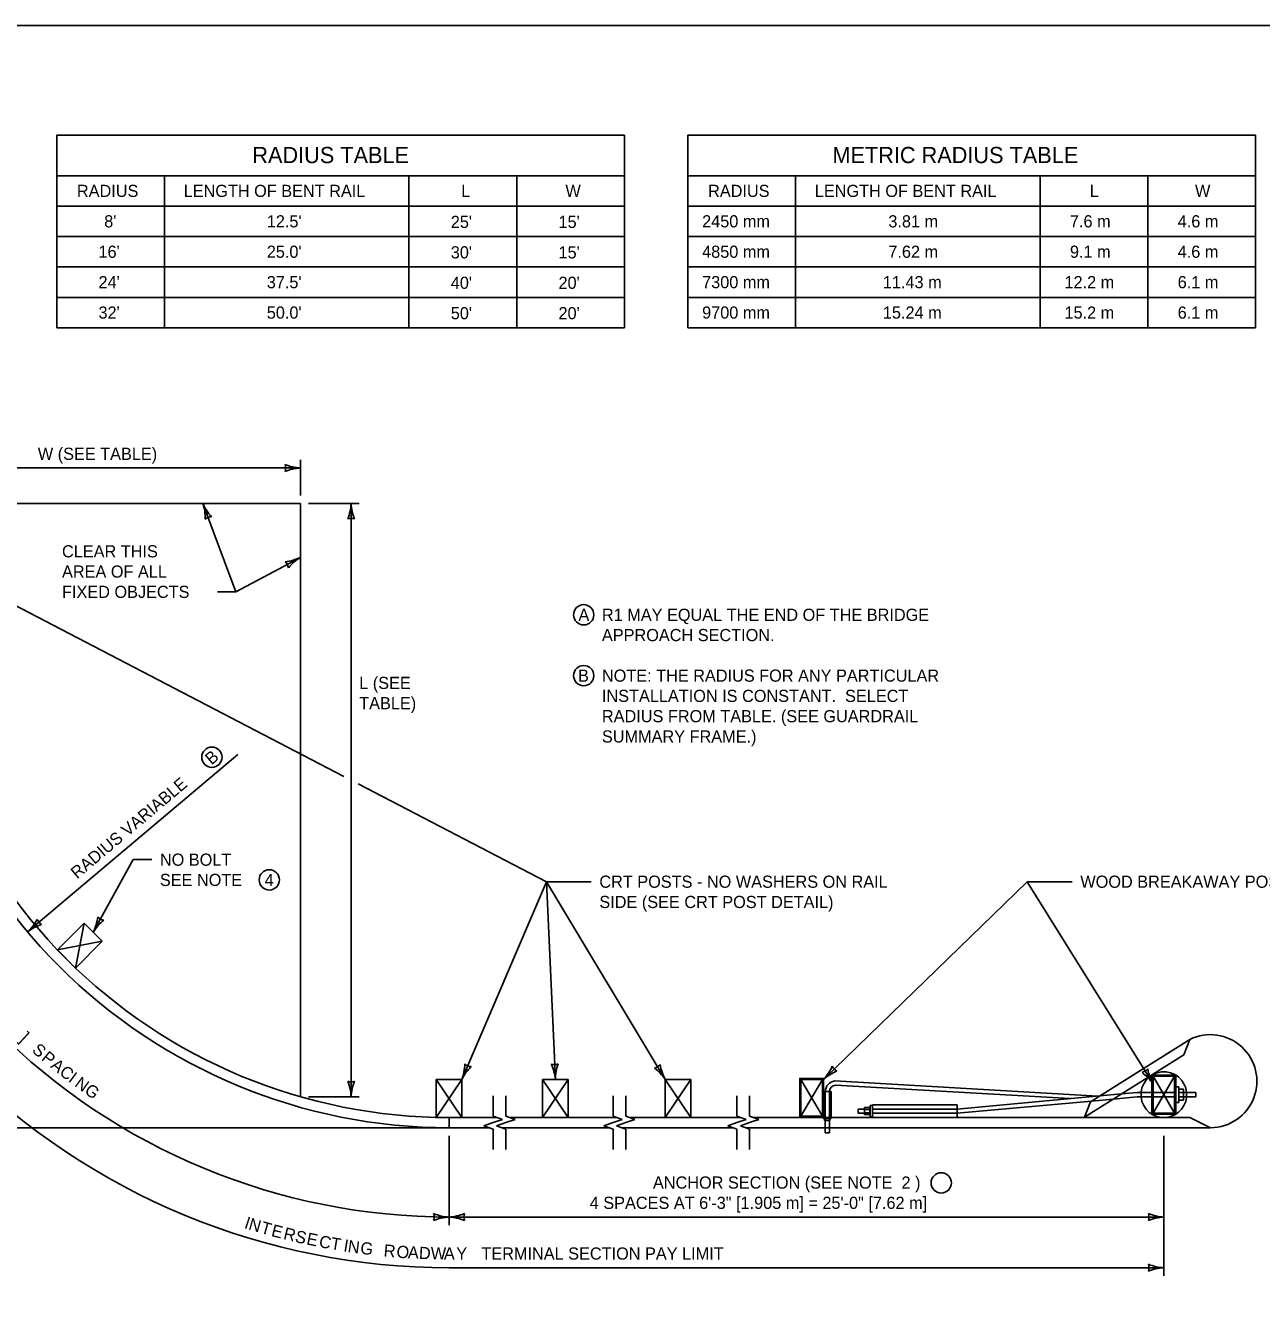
# Model space of a CAD drawing. Extents: x 49991.4 to 50021, y 49987.6 to 50011.4.
# Drawn here: x 50001.79 to 50007.89, y 49992.72 to 49999 of the extents above; entities that cross this region are included whole.
import ezdxf

# ---------------------------------------------------------------- set-up
doc = ezdxf.new("R2010")
doc.units = 0
for name, color, linetype in [('Level 1', 7, 'Continuous'), ('Level 2', 7, 'Continuous'), ('Level 3', 7, 'Continuous'), ('Level 4', 7, 'Continuous'), ('Level 6', 7, 'Continuous')]:
    doc.layers.add(name, color=color, linetype=linetype)

msp = doc.modelspace()

# ---------------------------------------------------------------- linework, layer by layer
at = {"layer": 'Level 1'}
for p, q in [((50003.1466, 49996.6418), (50001.2105, 49996.6418)), ((50003.1466, 49993.716), (50003.1466, 49996.6418)), ((50002.0803, 49994.5724), (50001.9477, 49994.4398)), ((50002.0802, 49994.5723), (50002.037, 49994.3504)), ((50002.1695, 49994.483), (50002.0803, 49994.5724)), ((50002.1695, 49994.483), (50001.9477, 49994.4398)), ((50002.1695, 49994.483), (50002.037, 49994.3504)), ((50001.9477, 49994.4398), (50002.037, 49994.3504)), ((50007.0428, 49993.6914), (50007.5328, 49993.9988)), ((50007.5041, 49993.9233), (50007.5328, 49993.9988)), ((50007.0141, 49993.6159), (50007.5041, 49993.9233)), ((50003.9428, 49993.8011), (50003.8166, 49993.8011)), ((50003.9428, 49993.6137), (50003.8166, 49993.8011)), ((50003.8166, 49993.6142), (50003.9428, 49993.8011)), ((50003.8166, 49993.6142), (50003.8166, 49993.8011)), ((50003.9428, 49993.6134), (50003.9428, 49993.8011)), ((50004.4671, 49993.8011), (50004.3408, 49993.8011)), ((50004.4671, 49993.6137), (50004.3408, 49993.8011)), ((50004.3408, 49993.6137), (50004.4671, 49993.8011)), ((50004.3408, 49993.6137), (50004.3408, 49993.8011)), ((50004.4671, 49993.6137), (50004.4671, 49993.8011)), ((50005.0721, 49993.8011), (50004.9458, 49993.8011)), ((50005.0721, 49993.6137), (50004.9458, 49993.8011)), ((50004.9458, 49993.6137), (50005.0721, 49993.8011)), ((50004.9458, 49993.6137), (50004.9458, 49993.8011)), ((50005.0721, 49993.6137), (50005.0721, 49993.8011)), ((50005.7214, 49993.8008), (50005.6153, 49993.6195)), ((50005.6153, 49993.8008), (50005.7214, 49993.6195)), ((50005.7829, 49993.7939), (50007.0798, 49993.7194)), ((50005.7851, 49993.7731), (50006.9421, 49993.7067)), ((50007.3517, 49993.817), (50007.4578, 49993.6357)), ((50007.4578, 49993.817), (50007.3517, 49993.6357)), ((50005.7271, 49993.7411), (50005.7638, 49993.7411)), ((50005.7271, 49993.6137), (50005.7271, 49993.7411)), ((50005.7638, 49993.6137), (50005.7638, 49993.7411)), ((50006.3848, 49993.6553), (50007.0887, 49993.7202)), ((50007.1557, 49993.7047), (50007.2729, 49993.7154)), ((50007.1965, 49993.7303), (50007.273, 49993.7372)), ((50007.3517, 49993.7154), (50007.2729, 49993.7154)), ((50007.3517, 49993.7372), (50007.273, 49993.7372)), ((50007.4635, 49993.7653), (50007.4782, 49993.7653)), ((50007.4782, 49993.7653), (50007.4782, 49993.6873)), ((50007.4782, 49993.7528), (50007.5023, 49993.7528)), ((50007.4782, 49993.7372), (50007.5628, 49993.7372)), ((50007.4782, 49993.7154), (50007.5628, 49993.7154)), ((50007.5023, 49993.7528), (50007.5023, 49993.6997)), ((50007.5628, 49993.7372), (50007.5628, 49993.7154)), ((50005.9281, 49993.6553), (50005.9291, 49993.6553)), ((50005.9291, 49993.6528), (50005.9546, 49993.6528)), ((50005.9678, 49993.6761), (50006.3848, 49993.6761)), ((50005.9678, 49993.6137), (50005.9678, 49993.6761)), ((50006.3848, 49993.6346), (50007.0484, 49993.6949)), ((50006.3848, 49993.6137), (50006.3848, 49993.6761)), ((50007.0141, 49993.6159), (50007.0428, 49993.6914)), ((50007.4635, 49993.6873), (50007.4782, 49993.6873)), ((50007.4782, 49993.6997), (50007.5023, 49993.6997)), ((50003.8797, 49993.6134), (50004.1177, 49993.6134)), ((50003.8797, 49993.5631), (50003.8797, 49993.6134)), ((50004.1794, 49993.6137), (50004.7084, 49993.6137)), ((50004.7709, 49993.6137), (50005.3197, 49993.6137)), ((50005.3822, 49993.6137), (50007.5328, 49993.6137)), ((50005.7271, 49993.6083), (50005.7271, 49993.6137)), ((50005.7271, 49993.6083), (50005.7638, 49993.6083)), ((50005.7638, 49993.6083), (50005.7638, 49993.6137)), ((50005.9281, 49993.6345), (50005.9291, 49993.6345)), ((50005.9291, 49993.637), (50005.9546, 49993.637)), ((50007.5328, 49993.6137), (50007.6356, 49993.5631)), ((50003.8797, 49993.5631), (50004.0768, 49993.5631)), ((50004.1393, 49993.5631), (50004.6683, 49993.5631)), ((50004.7308, 49993.5631), (50005.2796, 49993.5631)), ((50005.3421, 49993.5631), (50007.6356, 49993.5631)), ((50005.735, 49993.5631), (50005.735, 49993.5378)), ((50005.735, 49993.5378), (50005.7559, 49993.5378)), ((50005.7559, 49993.5631), (50005.7559, 49993.5378))]:
    msp.add_line(p, q, dxfattribs=at)
for points in [[(49999.3835, 49998.9992), (50016.7501, 49998.9992), (50016.7501, 49987.7988), (49999.3835, 49987.7988)], [(50005.6153, 49993.8008), (50005.7214, 49993.8008), (50005.7214, 49993.6195), (50005.6153, 49993.6195)], [(50007.3517, 49993.817), (50007.4578, 49993.817), (50007.4578, 49993.6357), (50007.3517, 49993.6357)], [(50005.9281, 49993.6553), (50005.9281, 49993.6345), (50005.8978, 49993.6345), (50005.8978, 49993.6553)], [(50005.9291, 49993.6625), (50005.9291, 49993.6281), (50005.9546, 49993.6281), (50005.9546, 49993.6625)], [(50005.9558, 49993.6727), (50005.9558, 49993.6164), (50005.9678, 49993.6164), (50005.9678, 49993.6727)], [(50005.7318, 49993.6083), (50005.7318, 49993.5994), (50005.7581, 49993.5994), (50005.7581, 49993.6083)]]:
    msp.add_lwpolyline(points, close=True, dxfattribs=at)
for points in [[(50005.6095, 49993.721), (50005.6095, 49993.8066), (50005.7271, 49993.8066), (50005.7271, 49993.6137), (50005.6095, 49993.6137), (50005.6095, 49993.721)], [(50007.3459, 49993.7372), (50007.3459, 49993.8228), (50007.4635, 49993.8228), (50007.4635, 49993.6299), (50007.3459, 49993.6299), (50007.3459, 49993.7154)], [(50007.3459, 49993.7154), (50007.3459, 49993.7372)]]:
    msp.add_lwpolyline(points, dxfattribs=at)
for centre, radius, start, end in [((50003.8796, 49996.2825), 2.7194, 180, 270.00211), ((50003.8796, 49996.2825), 2.6691, 180, 270.00108), ((50007.6341, 49993.7927), 0.2296, 270.3943, 116.15709), ((50007.4048, 49993.7263), 0.113, 185.54991, 185.5335), ((50007.284, 49993.8885), 0.0548, 284.01902, 319.74138), ((50007.1602, 49993.647), 0.233, 34.70751, 53.95736), ((50007.5452, 49993.8892), 0.2223, 189.33621, 209.51972), ((50005.7884, 49993.7408), 0.0534, 95.95713, 179.63592), ((50005.7884, 49993.7408), 0.0325, 95.95713, 179.40205)]:
    msp.add_arc(centre, radius, start, end, dxfattribs=at)
at = {"layer": 'Level 2'}
for p, q in [((50001.9444, 49998.4584), (50001.9444, 49997.5084)), ((50001.9444, 49998.4584), (50004.7446, 49998.4584)), ((50004.7446, 49998.4584), (50004.7446, 49997.5084)), ((50005.0573, 49998.4584), (50005.0573, 49997.5084)), ((50005.0573, 49998.4584), (50007.8575, 49998.4584)), ((50007.8575, 49998.4584), (50007.8575, 49997.5084)), ((50001.9444, 49998.2584), (50004.7446, 49998.2584)), ((50002.4758, 49998.2584), (50002.4758, 49998.1084)), ((50003.6819, 49998.2584), (50003.6819, 49997.5084)), ((50004.2133, 49998.2584), (50004.2133, 49997.5084)), ((50005.0573, 49998.2584), (50007.8575, 49998.2584)), ((50005.5887, 49998.2584), (50005.5887, 49998.1084)), ((50006.7948, 49998.2584), (50006.7948, 49997.5084)), ((50007.3262, 49998.2584), (50007.3262, 49997.5084)), ((50001.9444, 49998.1084), (50004.7446, 49998.1084)), ((50002.4758, 49998.1084), (50002.4758, 49997.9584)), ((50005.0573, 49998.1084), (50007.8575, 49998.1084)), ((50005.5887, 49998.1084), (50005.5887, 49997.9584)), ((50001.9444, 49997.9584), (50004.7446, 49997.9584)), ((50002.4758, 49997.9584), (50002.4758, 49997.8084)), ((50005.0573, 49997.9584), (50007.8575, 49997.9584)), ((50005.5887, 49997.9584), (50005.5887, 49997.8084)), ((50001.9444, 49997.8084), (50004.7446, 49997.8084)), ((50002.4758, 49997.8084), (50002.4758, 49997.6584)), ((50005.0573, 49997.8084), (50007.8575, 49997.8084)), ((50005.5887, 49997.8084), (50005.5887, 49997.6584)), ((50001.9444, 49997.6584), (50004.7446, 49997.6584)), ((50002.4758, 49997.6584), (50002.4758, 49997.5084)), ((50005.0573, 49997.6584), (50007.8575, 49997.6584)), ((50005.5887, 49997.6584), (50005.5887, 49997.5084)), ((50001.9444, 49997.5084), (50002.4758, 49997.5084)), ((50002.4758, 49997.5084), (50003.6819, 49997.5084)), ((50003.6819, 49997.5084), (50004.2133, 49997.5084)), ((50004.2133, 49997.5084), (50004.7446, 49997.5084)), ((50005.0573, 49997.5084), (50005.5887, 49997.5084)), ((50005.5887, 49997.5084), (50006.7948, 49997.5084)), ((50006.7948, 49997.5084), (50007.3262, 49997.5084)), ((50007.3262, 49997.5084), (50007.8575, 49997.5084))]:
    msp.add_line(p, q, dxfattribs=at)
for centre in [(50004.5436, 49996.0929), (50004.5436, 49995.7927), (50002.71, 49995.3904), (50002.9932, 49994.7853), (50006.3069, 49993.2912)]:
    msp.add_circle(centre, 0.05, dxfattribs=at)
at = {"layer": 'Level 3'}
for p, q in [((50003.1466, 49996.6818), (50003.1466, 49996.8568)), ((50001.2105, 49996.8168), (50003.1466, 49996.8168)), ((50002.8288, 49996.206), (50002.6657, 49996.6418)), ((50003.1866, 49996.6418), (50003.4366, 49996.6418)), ((50003.3966, 49993.716), (50003.3966, 49996.6418)), ((50002.8288, 49996.206), (50003.1466, 49996.3757)), ((50001.5855, 49996.2195), (50003.3612, 49995.2959)), ((50002.7377, 49996.206), (50002.8288, 49996.206)), ((50002.8383, 49995.404), (50001.8012, 49994.529)), ((50003.4321, 49995.259), (50004.3595, 49994.7766)), ((50002.3223, 49994.8853), (50002.1249, 49994.5277)), ((50002.3223, 49994.8853), (50002.4135, 49994.8853)), ((50004.3595, 49994.7766), (50003.9428, 49993.8011)), ((50004.3595, 49994.7766), (50004.4039, 49993.8011)), ((50004.3595, 49994.7766), (50004.9458, 49993.8011)), ((50004.3595, 49994.7766), (50004.5809, 49994.7766)), ((50006.7316, 49994.7766), (50005.7263, 49993.8011)), ((50006.7316, 49994.7766), (50007.3517, 49993.7796)), ((50006.7316, 49994.7766), (50006.953, 49994.7766)), ((50003.1866, 49993.716), (50003.4366, 49993.716)), ((50003.8797, 49993.5631), (50001.1602, 49993.5631)), ((50003.8796, 49993.5231), (50003.8796, 49993.0828)), ((50007.4047, 49993.5231), (50007.4047, 49992.8328)), ((50003.8796, 49993.1228), (50007.4047, 49993.1228)), ((50003.8796, 49992.8728), (50007.4047, 49992.8728))]:
    msp.add_line(p, q, dxfattribs=at)
for centre, radius, start, end in [((50003.1558, 49997.039), 0.2223, 247.45601, 267.63952), ((50003.0184, 49996.8168), 0.0548, 342.13882, 17.86118), ((50003.1581, 49996.5841), 0.233, 92.82731, 112.07716), ((50002.4545, 49996.5726), 0.2223, 357.96824, 18.15175), ((50002.8797, 49996.7341), 0.233, 203.33954, 222.58939), ((50003.1745, 49996.651), 0.2223, 337.45601, 357.63952), ((50003.6294, 49996.6533), 0.233, 182.82731, 202.07716), ((50002.7107, 49996.5218), 0.0548, 92.65105, 128.37341), ((50003.3966, 49996.5136), 0.0548, 72.13882, 107.86118), ((50003.0501, 49996.576), 0.2223, 275.54361, 295.72712), ((50003.0335, 49996.3153), 0.0548, 10.22642, 45.94878), ((50003.2663, 49996.1758), 0.233, 120.91491, 140.16476), ((50003.8796, 49996.2825), 3.4097, 180, 270.00108), ((50003.8796, 49996.2825), 3.1597, 180, 270.00108), ((50001.6423, 49994.6994), 0.233, 312.98115, 332.231), ((50001.8992, 49994.6116), 0.0548, 202.29266, 238.01502), ((50001.9156, 49994.6301), 0.233, 333.92245, 353.1723), ((50002.315, 49994.4123), 0.2223, 128.55115, 148.73466), ((50002.1869, 49994.64), 0.0548, 223.23396, 258.95632), ((50001.9374, 49994.3533), 0.2223, 107.60985, 127.79336), ((50003.7243, 49993.882), 0.233, 339.69681, 358.94666), ((50004.1435, 49993.7055), 0.2223, 134.32551, 154.50901), ((50003.9932, 49993.919), 0.0548, 229.00831, 264.73068), ((50004.3981, 49993.9292), 0.0548, 254.74484, 290.46721), ((50004.172, 49993.7791), 0.233, 5.43334, 24.68319), ((50004.6263, 49993.8021), 0.2223, 160.06204, 180.24554), ((50004.8798, 49993.911), 0.0548, 283.14574, 318.86811), ((50004.7523, 49993.6714), 0.233, 33.83424, 53.08409), ((50005.141, 49993.9077), 0.2223, 188.46294, 208.64644), ((50005.556, 49993.9601), 0.233, 316.96539, 336.21524), ((50005.8745, 49993.6353), 0.2223, 111.59409, 131.7776), ((50005.8184, 49993.8904), 0.0548, 206.2769, 241.99926), ((50003.3966, 49993.8443), 0.0548, 252.13882, 287.86118), ((50003.1639, 49993.7045), 0.233, 2.82731, 22.07716), ((50003.6188, 49993.7069), 0.2223, 157.45601, 177.63952), ((50003.8888, 49993.3449), 0.2223, 247.45709, 267.6406), ((50003.7514, 49993.1228), 0.0548, 342.1399, 17.86226), ((50003.8911, 49992.8901), 0.233, 92.82839, 112.07824), ((50003.8682, 49993.3555), 0.233, 272.82731, 292.07716), ((50003.8705, 49992.9007), 0.2223, 67.45601, 87.63952), ((50004.0079, 49993.1228), 0.0548, 162.13882, 197.86118), ((50007.4139, 49993.345), 0.2223, 247.45601, 267.63952), ((50007.2765, 49993.1228), 0.0548, 342.13882, 17.86118), ((50007.4162, 49992.8901), 0.233, 92.82731, 112.07716), ((50007.4139, 49993.095), 0.2223, 247.45601, 267.63952), ((50007.2765, 49992.8728), 0.0548, 342.13882, 17.86118), ((50007.4162, 49992.6401), 0.233, 92.82731, 112.07716)]:
    msp.add_arc(centre, radius, start, end, dxfattribs=at)
at = {"layer": 'Level 4'}
for p, q in [((50005.735, 49993.7411), (50005.735, 49993.5631)), ((50005.7559, 49993.7411), (50005.7559, 49993.5631)), ((50007.0887, 49993.7202), (50007.1965, 49993.7303)), ((50007.3517, 49993.7372), (50007.4635, 49993.7372)), ((50007.3517, 49993.7154), (50007.4635, 49993.7154)), ((50005.9678, 49993.6553), (50006.3848, 49993.6553)), ((50007.0484, 49993.6949), (50007.1557, 49993.7047)), ((50005.9678, 49993.6346), (50006.3848, 49993.6346))]:
    msp.add_line(p, q, dxfattribs=at)
at = {"layer": 'Level 6'}
for p, q in [((50004.0968, 49993.6208), (50004.0968, 49993.7208)), ((50004.1593, 49993.6208), (50004.1593, 49993.7208)), ((50004.6883, 49993.6208), (50004.6883, 49993.7208)), ((50004.7508, 49993.6208), (50004.7508, 49993.7208)), ((50005.2996, 49993.6208), (50005.2996, 49993.7208)), ((50005.3621, 49993.6208), (50005.3621, 49993.7208)), ((50004.0968, 49993.5884), (50004.0511, 49993.5722)), ((50004.1425, 49993.6046), (50004.0968, 49993.6208)), ((50004.1425, 49993.6046), (50004.0968, 49993.5884)), ((50004.1593, 49993.5884), (50004.1136, 49993.5722)), ((50004.205, 49993.6046), (50004.1593, 49993.6208)), ((50004.205, 49993.6046), (50004.1593, 49993.5884)), ((50004.6883, 49993.5884), (50004.6426, 49993.5722)), ((50004.734, 49993.6046), (50004.6883, 49993.6208)), ((50004.734, 49993.6046), (50004.6883, 49993.5884)), ((50004.7508, 49993.5884), (50004.7051, 49993.5722)), ((50004.7965, 49993.6046), (50004.7508, 49993.6208)), ((50004.7965, 49993.6046), (50004.7508, 49993.5884)), ((50005.2996, 49993.5884), (50005.2539, 49993.5722)), ((50005.3453, 49993.6046), (50005.2996, 49993.6208)), ((50005.3453, 49993.6046), (50005.2996, 49993.5884)), ((50005.3621, 49993.5884), (50005.3164, 49993.5722)), ((50005.4078, 49993.6046), (50005.3621, 49993.6208)), ((50005.4078, 49993.6046), (50005.3621, 49993.5884)), ((50004.0968, 49993.556), (50004.0511, 49993.5722)), ((50004.0968, 49993.556), (50004.0968, 49993.456)), ((50004.1593, 49993.556), (50004.1136, 49993.5722)), ((50004.1593, 49993.556), (50004.1593, 49993.456)), ((50004.6883, 49993.556), (50004.6426, 49993.5722)), ((50004.6883, 49993.556), (50004.6883, 49993.456)), ((50004.7508, 49993.556), (50004.7051, 49993.5722)), ((50004.7508, 49993.556), (50004.7508, 49993.456)), ((50005.2996, 49993.556), (50005.2539, 49993.5722)), ((50005.2996, 49993.556), (50005.2996, 49993.456)), ((50005.3621, 49993.556), (50005.3164, 49993.5722)), ((50005.3621, 49993.556), (50005.3621, 49993.456))]:
    msp.add_line(p, q, dxfattribs=at)

# ---------------------------------------------------------------- texts
at = {"layer": 'Level 2'}
for s, height, p in [('RADIUS TABLE', 0.08, (50002.9094, 49998.3202)), ('METRIC RADIUS TABLE', 0.08, (50005.7703, 49998.3202)), ('RADIUS', 0.06, (50002.0443, 49998.1534)), ('LENGTH OF BENT RAIL', 0.06, (50002.5707, 49998.1534)), ('L', 0.06, (50003.9394, 49998.1534)), ('W', 0.06, (50004.4536, 49998.1534)), ('RADIUS', 0.06, (50005.1572, 49998.1534)), ('LENGTH OF BENT RAIL', 0.06, (50005.6836, 49998.1534)), ('L', 0.06, (50007.0393, 49998.1534)), ('W', 0.06, (50007.5587, 49998.1534)), (" 8'", 0.06, (50002.1566, 49998.0034)), ("12.5'", 0.06, (50002.9807, 49998.0034)), ("25'", 0.06, (50003.8882, 49998.0004)), ("15'", 0.06, (50004.4195, 49998.0004)), ('2450 mm', 0.06, (50005.1278, 49998.0034)), ('3.81 m', 0.06, (50006.0462, 49998.0034)), ('7.6 m', 0.06, (50006.9418, 49998.0034)), ('4.6 m', 0.06, (50007.4732, 49998.0034)), ("16'", 0.06, (50002.1507, 49997.8534)), ("25.0'", 0.06, (50002.9807, 49997.8534)), ('4850 mm', 0.06, (50005.1278, 49997.8534)), ('7.62 m', 0.06, (50006.0462, 49997.8534)), ('9.1 m', 0.06, (50006.9418, 49997.8534)), ('4.6 m', 0.06, (50007.4732, 49997.8534)), ("30'", 0.06, (50003.8882, 49997.8504)), ("15'", 0.06, (50004.4195, 49997.8504)), ("24'", 0.06, (50002.1508, 49997.7033)), ("37.5'", 0.06, (50002.9807, 49997.7033)), ("40'", 0.06, (50003.8882, 49997.7003)), ("20'", 0.06, (50004.4195, 49997.7003)), ('7300 mm', 0.06, (50005.1278, 49997.7034)), ('11.43 m', 0.06, (50006.0192, 49997.7034)), ('12.2 m', 0.06, (50006.9149, 49997.7034)), ('6.1 m', 0.06, (50007.4732, 49997.7034)), ("32'", 0.06, (50002.1508, 49997.5534)), ("50.0'", 0.06, (50002.9807, 49997.5533)), ("50'", 0.06, (50003.8882, 49997.5503)), ("20'", 0.06, (50004.4195, 49997.5503)), ('9700 mm', 0.06, (50005.1278, 49997.5534)), ('15.24 m', 0.06, (50006.0192, 49997.5534)), ('15.2 m', 0.06, (50006.9149, 49997.5534)), ('6.1 m', 0.06, (50007.4732, 49997.5534)), ('W (SEE TABLE)', 0.06, (50001.8516, 49996.8568)), ('CLEAR THIS', 0.06, (50001.9708, 49996.376)), ('AREA OF ALL', 0.06, (50001.9708, 49996.276)), ('FIXED OBJECTS', 0.06, (50001.9708, 49996.176)), ('A', 0.06, (50004.5179, 49996.063)), ('R1 MAY EQUAL THE END OF THE BRIDGE', 0.06, (50004.6336, 49996.0629)), ('APPROACH SECTION.', 0.06, (50004.6336, 49995.9629)), ('L (SEE', 0.06, (50003.4366, 49995.7269)), ('B', 0.06, (50004.5159, 49995.7627)), ('NOTE: THE RADIUS FOR ANY PARTICULAR', 0.06, (50004.6336, 49995.7629)), ('INSTALLATION IS CONSTANT.  SELECT', 0.06, (50004.6336, 49995.6629)), ('TABLE)', 0.06, (50003.4366, 49995.6269)), ('RADIUS FROM TABLE. (SEE GUARDRAIL', 0.06, (50004.6336, 49995.5629)), ('SUMMARY FRAME.)', 0.06, (50004.6336, 49995.4629)), ('NO BOLT', 0.06, (50002.4535, 49994.8553)), ('SEE NOTE', 0.06, (50002.4535, 49994.7553)), ('4', 0.06, (50002.9704, 49994.7553)), ('CRT POSTS - NO WASHERS ON RAIL', 0.06, (50004.6209, 49994.7466)), ('WOOD BREAKAWAY POSTS', 0.06, (50006.993, 49994.7466)), ('SIDE (SEE CRT POST DETAIL)', 0.06, (50004.6209, 49994.6466)), ('ANCHOR SECTION (SEE NOTE  2 )', 0.06, (50004.8852, 49993.2628)), ('4 SPACES AT 6\'-3" [1.905 m] = 25\'-0" [7.62 m]', 0.06, (50004.5735, 49993.1628)), ('Y', 0.06, (50003.9154, 49992.9128)), ('TERMINAL SECTION PAY LIMIT', 0.06, (50004.0392, 49992.9128))]:
    msp.add_text(s, height=height, dxfattribs=at).set_placement(p)
for s, rotation, p in [('B', 40.23662, (50002.7082, 49995.3496)), ('RADIUS VARIABLE', 40.15395, (50002.0454, 49994.7873)), (']', 317.62817, (50001.7572, 49993.9959)), ('S', 319.16238, (50001.8192, 49993.9399)), ('P', 320.27672, (50001.8652, 49993.9002)), ('A', 321.35739, (50001.9105, 49993.8627)), ('C', 322.36721, (50001.9534, 49993.8283)), ('I', 323.40005, (50001.998, 49993.794)), ('N', 324.11312, (50002.0291, 49993.7708)), ('G', 325.20531, (50002.0773, 49993.736)), ('I', 342.01686, (50002.8661, 49993.0693)), ('N', 344.16662, (50002.8868, 49993.0621)), ('T', 344.16662, (50002.9465, 49993.0451)), ('E', 346.31638, (50002.9995, 49993.0293)), ('R', 346.31638, (50003.0592, 49993.0148)), ('S', 346.31638, (50003.1163, 49993.0008)), ('E', 348.46614, (50003.1733, 49992.9881)), ('C', 348.46614, (50003.2347, 49992.9756)), ('T', 350.61589, (50003.2926, 49992.9647)), ('I', 350.61589, (50003.3563, 49992.9541)), ('N', 352.76565, (50003.3777, 49992.95)), ('G', 352.76565, (50003.4395, 49992.9422)), ('R', 354.91541, (50003.5553, 49992.9289)), ('O', 354.91541, (50003.6184, 49992.9234)), ('A', 357.06516, (50003.6754, 49992.9195)), ('D', 357.06516, (50003.7299, 49992.9167)), ('W', 359.07056, (50003.789, 49992.9143)), ('A', 359.07056, (50003.8539, 49992.9132))]:
    msp.add_text(s, height=0.06, rotation=rotation, dxfattribs=at).set_placement(p)

doc.saveas('drawing.dxf')
